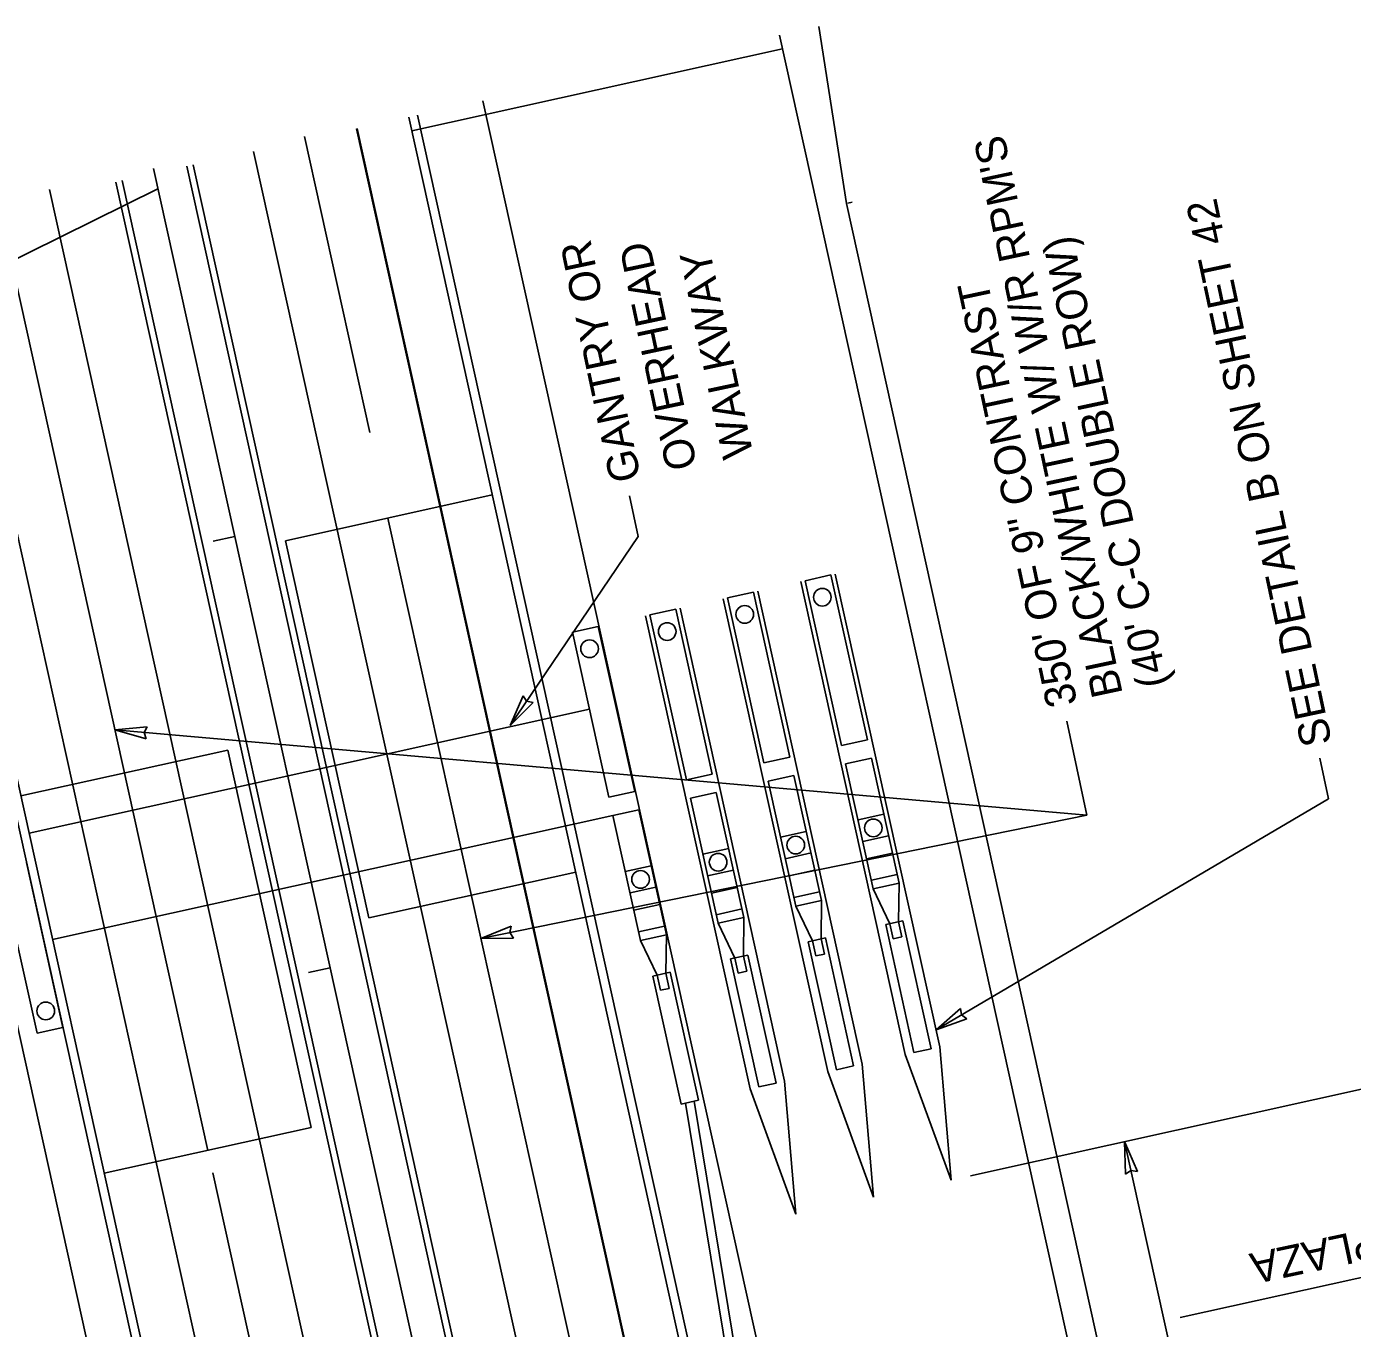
# Model space of a CAD drawing. Extents: x 578088 to 579220, y 1508751 to 1510399.
# Drawn here: x 578333.4 to 578633.8, y 1510059 to 1510353.9 of the extents above; entities that cross this region are included whole.
import ezdxf

# ---------------------------------------------------------------- set-up
doc = ezdxf.new("R2010")
doc.units = 0
for name, color, linetype in [('1', 7, 'Continuous'), ('18', 7, 'Continuous'), ('2', 7, 'Continuous'), ('28', 7, 'Continuous'), ('41', 7, 'Continuous'), ('46', 7, 'Continuous'), ('52', 7, 'Continuous')]:
    doc.layers.add(name, color=color, linetype=linetype)

msp = doc.modelspace()

# ---------------------------------------------------------------- linework, layer by layer
at = {"layer": '1'}
for p, q in [((578639.69, 1509066.69), (578362.17, 1510321.74)), ((578559.88, 1509205.29), (578315.3, 1510311.37))]:
    msp.add_line(p, q, dxfattribs=at)
at = {"layer": '18'}
for p, q in [((578612.63, 1509860.67), (578504, 1510351.92)), ((578545.42, 1509845.81), (578436.79, 1510337.06)), ((578516.77, 1509839.48), (578408.15, 1510330.73)), ((578471.12, 1509495.56), (578291.87, 1510306.19)), ((578415.3, 1510242.58), (578497.77, 1509869.64)), ((578532.51, 1510121.1), (578508.83, 1510228.18)), ((578509.81, 1510228.4), (578515.67, 1510229.69)), ((578518.07, 1510191.05), (578509.81, 1510228.4)), ((578523.93, 1510192.35), (578515.67, 1510229.69)), ((578540.32, 1510122.83), (578516.64, 1510229.91)), ((578514.93, 1510117.21), (578491.26, 1510224.3)), ((578492.23, 1510224.51), (578498.09, 1510225.81)), ((578500.49, 1510187.16), (578492.23, 1510224.51)), ((578506.35, 1510188.46), (578498.09, 1510225.81)), ((578522.75, 1510118.94), (578499.07, 1510226.02)), ((578474.66, 1510220.63), (578480.52, 1510221.92)), ((578488.77, 1510184.57), (578480.52, 1510221.92)), ((578505.17, 1510115.05), (578481.49, 1510222.14)), ((578497.36, 1510113.33), (578473.68, 1510220.41)), ((578482.92, 1510183.28), (578474.66, 1510220.63)), ((578457.08, 1510216.74), (578462.94, 1510218.03)), ((578465.34, 1510179.39), (578457.08, 1510216.74)), ((578471.2, 1510180.69), (578462.94, 1510218.03)), ((578518.07, 1510191.05), (578523.93, 1510192.35)), ((578500.49, 1510187.16), (578506.35, 1510188.46)), ((578518.98, 1510186.9), (578524.84, 1510188.2)), ((578525.25, 1510158.58), (578518.98, 1510186.9)), ((578531.1, 1510159.88), (578524.84, 1510188.2)), ((578482.92, 1510183.28), (578488.77, 1510184.57)), ((578501.41, 1510183.01), (578507.27, 1510184.31)), ((578507.67, 1510154.7), (578501.41, 1510183.01)), ((578513.53, 1510155.99), (578507.27, 1510184.31)), ((578465.34, 1510179.39), (578471.2, 1510180.69)), ((578483.83, 1510179.13), (578489.69, 1510180.42)), ((578495.95, 1510152.11), (578489.69, 1510180.42)), ((578466.26, 1510175.24), (578472.12, 1510176.54)), ((578478.38, 1510148.22), (578472.12, 1510176.54)), ((578490.09, 1510150.81), (578483.83, 1510179.13)), ((578472.52, 1510146.93), (578466.26, 1510175.24)), ((578521.79, 1510174.21), (578527.65, 1510175.5)), ((578504.22, 1510170.32), (578510.07, 1510171.62)), ((578522.87, 1510169.32), (578528.73, 1510170.62)), ((578486.64, 1510166.43), (578492.5, 1510167.73)), ((578333.43, 1510164.56), (578341.69, 1510127.21)), ((578505.3, 1510165.44), (578511.15, 1510166.73)), ((578523.73, 1510165.42), (578529.59, 1510166.71)), ((578327.57, 1510163.27), (578335.83, 1510125.92)), ((578469.06, 1510162.55), (578474.92, 1510163.84)), ((578487.72, 1510161.55), (578493.58, 1510162.85)), ((578506.16, 1510161.53), (578512.02, 1510162.83)), ((578524.81, 1510160.54), (578530.67, 1510161.83)), ((578470.14, 1510157.67), (578476, 1510158.96)), ((578488.58, 1510157.65), (578494.44, 1510158.94)), ((578525.25, 1510158.58), (578531.1, 1510159.88)), ((578525.25, 1510158.58), (578529.03, 1510150.72)), ((578531.1, 1510159.88), (578530.99, 1510151.15)), ((578507.24, 1510156.65), (578513.1, 1510157.95)), ((578507.67, 1510154.7), (578513.53, 1510155.99)), ((578513.53, 1510155.99), (578513.41, 1510147.26)), ((578471.01, 1510153.76), (578476.87, 1510155.06)), ((578489.66, 1510152.76), (578495.52, 1510154.06)), ((578507.67, 1510154.7), (578511.46, 1510146.83)), ((578472.09, 1510148.88), (578477.95, 1510150.17)), ((578490.09, 1510150.81), (578495.95, 1510152.11)), ((578490.09, 1510150.81), (578493.88, 1510142.94)), ((578495.95, 1510152.11), (578495.84, 1510143.38)), ((578528.06, 1510150.5), (578531.96, 1510151.36)), ((578534.46, 1510121.53), (578528.06, 1510150.5)), ((578529.79, 1510147.3), (578529.03, 1510150.72)), ((578531.74, 1510147.73), (578530.99, 1510151.15)), ((578538.37, 1510122.39), (578531.96, 1510151.36)), ((578472.52, 1510146.93), (578478.38, 1510148.22)), ((578472.52, 1510146.93), (578476.31, 1510139.06)), ((578478.38, 1510148.22), (578478.26, 1510139.49)), ((578510.48, 1510146.61), (578514.39, 1510147.48)), ((578516.89, 1510117.64), (578510.48, 1510146.61)), ((578512.21, 1510143.41), (578511.46, 1510146.83)), ((578514.17, 1510143.84), (578513.41, 1510147.26)), ((578520.79, 1510118.51), (578514.39, 1510147.48)), ((578529.79, 1510147.3), (578531.74, 1510147.73)), ((578492.91, 1510142.73), (578496.81, 1510143.59)), ((578496.59, 1510139.96), (578495.84, 1510143.38)), ((578503.22, 1510114.62), (578496.81, 1510143.59)), ((578512.21, 1510143.41), (578514.17, 1510143.84)), ((578499.31, 1510113.76), (578492.91, 1510142.73)), ((578494.64, 1510139.53), (578493.88, 1510142.94)), ((578475.33, 1510138.84), (578479.24, 1510139.71)), ((578481.74, 1510109.87), (578475.33, 1510138.84)), ((578477.06, 1510135.64), (578476.31, 1510139.06)), ((578479.02, 1510136.07), (578478.26, 1510139.49)), ((578485.64, 1510110.74), (578479.24, 1510139.71)), ((578494.64, 1510139.53), (578496.59, 1510139.96)), ((578477.06, 1510135.64), (578479.02, 1510136.07)), ((578341.69, 1510127.21), (578335.83, 1510125.92)), ((578534.46, 1510121.53), (578538.37, 1510122.39)), ((578540.32, 1510122.83), (578542.89, 1510092.67)), ((578532.51, 1510121.1), (578542.89, 1510092.67)), ((578514.93, 1510117.21), (578525.32, 1510088.78)), ((578516.89, 1510117.64), (578520.79, 1510118.51)), ((578522.75, 1510118.94), (578525.32, 1510088.78)), ((578497.36, 1510113.33), (578507.74, 1510084.9)), ((578499.31, 1510113.76), (578503.22, 1510114.62)), ((578505.17, 1510115.05), (578507.74, 1510084.9)), ((578481.74, 1510109.87), (578485.64, 1510110.74)), ((578659.48, 1508810.53), (578375.62, 1510094.27))]:
    msp.add_line(p, q, dxfattribs=at)
for centre in [(578513.71, 1510224.65), (578496.13, 1510220.77), (578478.56, 1510216.88), (578460.98, 1510212.99), (578525.26, 1510172.41), (578507.68, 1510168.53), (578490.11, 1510164.64), (578472.53, 1510160.75), (578337.79, 1510130.96)]:
    msp.add_circle(centre, 2, dxfattribs=at)
at = {"layer": '2'}
for p, q in [((578504.67, 1510348.88), (578420.7, 1510330.31)), ((578528.65, 1509842.11), (578420.03, 1510333.36)), ((578515.82, 1509909.43), (578421.98, 1510333.79)), ((578516.94, 1509839.51), (578408.31, 1510330.77)), ((578411.23, 1510261.98), (578396.41, 1510329.02)), ((578493.5, 1509834.33), (578384.88, 1510325.58)), ((578482.83, 1509498.15), (578303.59, 1510308.78)), ((578480.88, 1509497.72), (578301.64, 1510308.35)), ((578438.95, 1510247.81), (578392.08, 1510237.44)), ((578410.97, 1510152.01), (578392.08, 1510237.44)), ((578460.94, 1510199.29), (578334.01, 1510171.22)), ((578379.01, 1510190), (578332.14, 1510179.64)), ((578379.01, 1510190), (578397.9, 1510104.57)), ((578466.26, 1510175.24), (578339.32, 1510147.17)), ((578457.84, 1510162.37), (578410.97, 1510152.01)), ((578482.71, 1510110.09), (578484.67, 1510110.52)), ((578523.79, 1509873.37), (578484.67, 1510110.52)), ((578515.82, 1509909.43), (578482.71, 1510110.09)), ((578397.9, 1510104.57), (578351.04, 1510094.2))]:
    msp.add_line(p, q, dxfattribs=at)
at = {"layer": '28'}
for p, q in [((578380.6, 1510238.38), (578375.72, 1510237.31)), ((578402.19, 1510140.74), (578397.31, 1510139.66))]:
    msp.add_line(p, q, dxfattribs=at)
at = {"layer": '41'}
for p, q in [((578612.63, 1509860.67), (578504, 1510351.91)), ((578612.63, 1509860.67), (578504, 1510351.91)), ((578612.63, 1509860.67), (578504, 1510351.91)), ((578374.47, 1510099.38), (578326.92, 1510314.41)), ((578671.2, 1508813.02), (578338.64, 1510317))]:
    msp.add_line(p, q, dxfattribs=at)
at = {"layer": '46'}
for p, q in [((578519.21, 1510313.84), (578512.91, 1510353.89)), ((578369.74, 1510322.24), (578478.37, 1509830.99)), ((578371.21, 1510322.56), (578479.83, 1509831.31)), ((578440.67, 1509925.07), (578353.63, 1510318.68)), ((578442.13, 1509925.39), (578355.1, 1510319)), ((578578.52, 1510045.32), (578519.21, 1510313.84)), ((578520.43, 1510314.11), (578519.46, 1510313.9))]:
    msp.add_line(p, q, dxfattribs=at)
at = {"layer": '52'}
for p, q in [((578167.13, 1510220.3), (578363.2, 1510317.1)), ((578470.02, 1510247.65), (578471.98, 1510238.42)), ((578471.98, 1510238.42), (578442.96, 1510195.58)), ((578445.91, 1510202.34), (578442.96, 1510195.58)), ((578442.96, 1510195.58), (578448.19, 1510200.8)), ((578446.72, 1510201.13), (578445.91, 1510202.34)), ((578448.19, 1510200.8), (578446.72, 1510201.13)), ((578360.76, 1510195.3), (578353.42, 1510194.59)), ((578353.42, 1510194.59), (578573.61, 1510175.29)), ((578353.42, 1510194.59), (578360.52, 1510192.56)), ((578360.09, 1510194), (578360.76, 1510195.3)), ((578569.08, 1510196.59), (578573.61, 1510175.29)), ((578360.52, 1510192.56), (578360.09, 1510194)), ((578626.44, 1510188.21), (578628.4, 1510178.99)), ((578628.4, 1510178.99), (578539.47, 1510126.68)), ((578436.35, 1510147.38), (578573.61, 1510175.29)), ((578443.19, 1510150.15), (578436.35, 1510147.38)), ((578442.92, 1510148.71), (578443.19, 1510150.15)), ((578436.35, 1510147.38), (578443.74, 1510147.45)), ((578443.74, 1510147.45), (578442.92, 1510148.71)), ((578545.03, 1510131.51), (578539.47, 1510126.68)), ((578545.25, 1510130.07), (578545.03, 1510131.51)), ((578539.47, 1510126.68), (578546.43, 1510129.14)), ((578546.43, 1510129.14), (578545.25, 1510130.07)), ((578676.4, 1510122.19), (578547.24, 1510093.63)), ((578582.18, 1510101.36), (578582.38, 1510093.98)), ((578585.07, 1510094.57), (578582.18, 1510101.36)), ((578582.18, 1510101.36), (578608.44, 1509982.6)), ((578582.38, 1510093.98), (578583.63, 1510094.81)), ((578583.63, 1510094.81), (578585.07, 1510094.57)), ((578699.43, 1510084.7), (578594.76, 1510061.55))]:
    msp.add_line(p, q, dxfattribs=at)

# ---------------------------------------------------------------- texts
for s, rotation, p in [("BLACK/WHITE W/ W/R RPM'S", 102, (578581.79, 1510202.77)), ('SEE DETAIL B ON SHEET 42', 102, (578629.18, 1510191.69)), ('GANTRY OR', 102, (578472.67, 1510251.54)), ("(40' C-C DOUBLE ROW)", 102, (578592.06, 1510204.95)), ('OVERHEAD', 102, (578485.39, 1510254.24)), ('WALKWAY', 102, (578498.11, 1510256.95)), ('350\' OF 9" CONTRAST', 102, (578571.52, 1510200.59)), ('BEGIN TOLL PLAZA', 192, (578695.64, 1510094.08))]:
    msp.add_text(s, height=7, rotation=rotation, dxfattribs=at).set_placement(p)

doc.saveas('drawing.dxf')
